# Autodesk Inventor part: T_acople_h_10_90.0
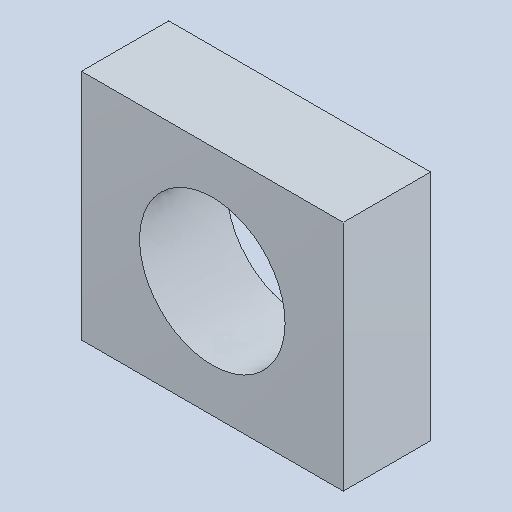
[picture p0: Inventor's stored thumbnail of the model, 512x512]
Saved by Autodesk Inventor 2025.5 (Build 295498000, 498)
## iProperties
Created: 2026-10
Part Number: T_acople_h_10_90.0
Material: Genérico
Document SubType Name: Modeling
Designer: Luis M
Density: 1 g/cm^3
Appearance: Valor por defecto
Author: Luis M
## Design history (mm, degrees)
feature "Base1"
node "Sólido1"
